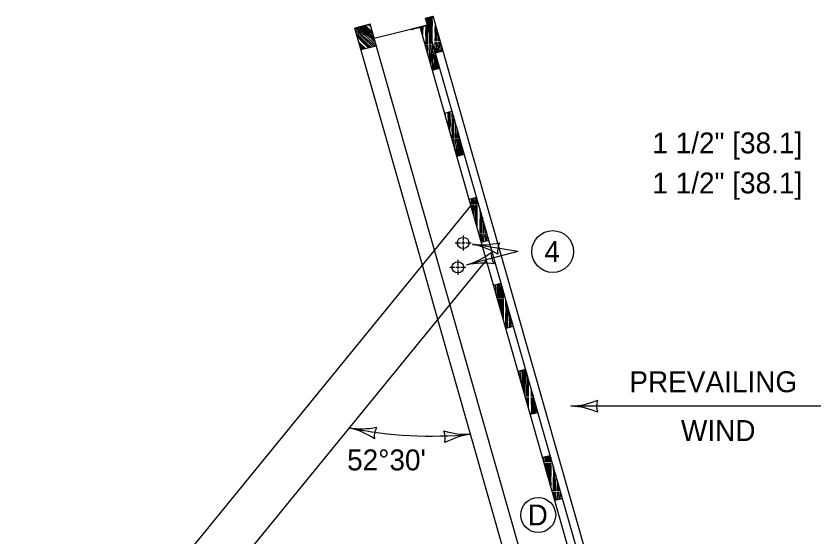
# Model space of a CAD drawing. Extents: x 49991.4 to 50021, y 49987.6 to 50011.4.
# Drawn here: x 50011.907 to 50014.217, y 49995.05 to 49996.545 of the extents above; entities that cross this region are included whole.
import ezdxf

# ---------------------------------------------------------------- set-up
doc = ezdxf.new("R2010")
doc.units = 0
for name, color, linetype in [('Level 1', 7, 'Continuous'), ('Level 2', 7, 'Continuous'), ('Level 3', 7, 'Continuous'), ('Level 4', 7, 'Continuous'), ('Level 5', 7, 'Continuous')]:
    doc.layers.add(name, color=color, linetype=linetype)

msp = doc.modelspace()

# ---------------------------------------------------------------- linework, layer by layer
at = {"layer": 'Level 1'}
for p, q in [((50013.4086, 49995.3946), (50013.0823, 49996.5389)), ((50013.0824, 49996.539), (50013.1042, 49996.5446)), ((50013.7582, 49994.2501), (50013.1042, 49996.5446)), ((50012.9234, 49996.5211), (50012.8797, 49996.51)), ((50012.8797, 49996.51), (50012.9234, 49996.5211)), ((50013.0736, 49995.8297), (50012.8797, 49996.51)), ((50012.938, 49996.3055), (50012.8797, 49996.51)), ((50012.941, 49996.4593), (50012.9234, 49996.5211)), ((50013.6869, 49993.8419), (50012.9235, 49996.5211)), ((50013.0882, 49996.5185), (50013.0008, 49996.4965)), ((50013.0408, 49996.5065), (50013.0882, 49996.5185)), ((50013.7112, 49994.2501), (50013.0664, 49996.5131)), ((50013.0008, 49996.4965), (50012.9351, 49996.48)), ((50013.0008, 49996.4965), (50013.0008, 49996.4965)), ((50013.0008, 49996.4965), (50013.0008, 49996.4965)), ((50012.8973, 49996.4483), (50012.941, 49996.4593)), ((50013.1107, 49996.4391), (50013.1327, 49996.4447)), ((50013.1016, 49996.3896), (50013.1234, 49996.3951)), ((50012.9849, 49996.3055), (50012.9761, 49996.3366)), ((50013.1367, 49996.2661), (50013.1586, 49996.2716)), ((50013.1718, 49996.1427), (50013.1937, 49996.1482)), ((50013.2071, 49996.0193), (50013.2289, 49996.0248)), ((50013.2422, 49995.896), (50013.264, 49995.9015)), ((50011.1535, 49993.4768), (50013.1083, 49995.8723)), ((50013.2774, 49995.7725), (50013.2991, 49995.778)), ((50011.2191, 49993.3474), (50013.1526, 49995.7167)), ((50013.4195, 49994.6162), (50013.1179, 49995.6741)), ((50013.3125, 49995.6491), (50013.3343, 49995.6546)), ((50013.3476, 49995.5256), (50013.3696, 49995.5312)), ((50013.3828, 49995.4023), (50013.4047, 49995.4077)), ((50013.3828, 49995.4023), (50013.4047, 49995.4077)), ((50013.6196, 49994.654), (50013.4039, 49995.411)), ((50013.4181, 49995.2789), (50013.4398, 49995.2844)), ((50013.4532, 49995.1554), (50013.475, 49995.1609))]:
    msp.add_line(p, q, dxfattribs=at)
for points in [[(50013.0841, 49996.533), (50013.0851, 49996.5396), (50013.0851, 49996.5398)], [(50013.0868, 49996.5237), (50013.089, 49996.5396), (50013.089, 49996.5407)], [(50013.0897, 49996.5134), (50013.0898, 49996.5217), (50013.0908, 49996.5396), (50013.0907, 49996.5412)], [(50013.0927, 49996.5027), (50013.0933, 49996.5171), (50013.0933, 49996.5355), (50013.0929, 49996.5417)], [(50013.0963, 49996.4902), (50013.0964, 49996.4949), (50013.0966, 49996.5197), (50013.0962, 49996.5425)], [(50013.0985, 49996.4826), (50013.0989, 49996.4892), (50013.0993, 49996.5365), (50013.0989, 49996.5433)], [(50013.1014, 49996.4724), (50013.1016, 49996.4908), (50013.1014, 49996.5067), (50013.1018, 49996.5231), (50013.1016, 49996.5396), (50013.1015, 49996.5439)], [(50012.9354, 49996.458), (50012.9146, 49996.4769), (50012.8966, 49996.494), (50012.8904, 49996.5009), (50012.8802, 49996.5101)], [(50012.9407, 49996.4605), (50012.9187, 49996.4807), (50012.9124, 49996.4863), (50012.9069, 49996.4905), (50012.9025, 49996.4936), (50012.8969, 49996.4991), (50012.8931, 49996.5043), (50012.8871, 49996.5105), (50012.8861, 49996.5116)], [(50012.9386, 49996.4677), (50012.9267, 49996.4793), (50012.918, 49996.4876), (50012.9126, 49996.4914), (50012.9088, 49996.4935), (50012.9022, 49996.4997), (50012.8939, 49996.5104), (50012.891, 49996.5129)], [(50012.9368, 49996.4741), (50012.9316, 49996.4789), (50012.9194, 49996.4899), (50012.907, 49996.5001), (50012.8966, 49996.5129), (50012.8953, 49996.514)], [(50012.9359, 49996.4775), (50012.9329, 49996.4801), (50012.9207, 49996.4911), (50012.9105, 49996.5009), (50012.8979, 49996.5142), (50012.8974, 49996.5144)], [(50012.9346, 49996.4817), (50012.9307, 49996.4854), (50012.9165, 49996.4999), (50012.9027, 49996.5129), (50012.9, 49996.5151)], [(50012.9325, 49996.4889), (50012.9169, 49996.5039), (50012.9035, 49996.516)], [(50012.9312, 49996.4936), (50012.9069, 49996.5169)], [(50012.9299, 49996.498), (50012.918, 49996.5097), (50012.9095, 49996.5175)], [(50012.9255, 49996.5138), (50012.9242, 49996.5151), (50012.9186, 49996.5199)], [(50012.9239, 49996.5194), (50012.9222, 49996.5207)], [(50013.0665, 49996.5126), (50013.0665, 49996.513)], [(50013.0698, 49996.5014), (50013.0698, 49996.5105), (50013.0698, 49996.5138)], [(50013.0723, 49996.4926), (50013.0724, 49996.5145)], [(50013.0747, 49996.4835), (50013.0746, 49996.4974), (50013.075, 49996.5139), (50013.075, 49996.5151)], [(50013.0832, 49996.5173), (50013.0834, 49996.5135), (50013.0824, 49996.4941), (50013.0828, 49996.4818), (50013.0824, 49996.4629)], [(50013.0863, 49996.5179), (50013.0868, 49996.5105), (50013.0855, 49996.4996), (50013.0858, 49996.4844), (50013.0862, 49996.4629)], [(50013.0892, 49996.5153), (50013.0896, 49996.5107), (50013.0892, 49996.4977), (50013.0882, 49996.4958), (50013.0879, 49996.4923), (50013.0881, 49996.4629)], [(50013.1101, 49996.5242), (50013.1101, 49996.5227), (50013.109, 49996.5034), (50013.1096, 49996.4911), (50013.109, 49996.4722)], [(50013.113, 49996.514), (50013.1123, 49996.509), (50013.1124, 49996.4937), (50013.1131, 49996.4722)], [(50012.9312, 49996.4568), (50012.9073, 49996.4791), (50012.8952, 49996.4911), (50012.8875, 49996.4971), (50012.8839, 49996.5008), (50012.8814, 49996.5038)], [(50012.9248, 49996.4553), (50012.9086, 49996.4703), (50012.9061, 49996.4732), (50012.9055, 49996.475), (50012.896, 49996.4845), (50012.8843, 49996.4937)], [(50012.9226, 49996.4546), (50012.913, 49996.4635), (50012.9013, 49996.4741), (50012.8942, 49996.4826), (50012.8854, 49996.4896)], [(50013.0698, 49996.5013), (50013.0698, 49996.5014)], [(50013.0723, 49996.4926), (50013.0723, 49996.4926)], [(50013.0934, 49996.5001), (50013.0934, 49996.5003)], [(50013.0934, 49996.5001), (50013.0934, 49996.4992), (50013.0938, 49996.4629)], [(50013.0971, 49996.4876), (50013.0975, 49996.4629)], [(50013.1153, 49996.5057), (50013.115, 49996.5052), (50013.1146, 49996.5015), (50013.1149, 49996.4722)], [(50013.1206, 49996.4722), (50013.1204, 49996.4879)], [(50012.9189, 49996.4538), (50012.9129, 49996.4597), (50012.9034, 49996.468), (50012.8895, 49996.4824), (50012.8869, 49996.4845)], [(50012.91, 49996.4516), (50012.9076, 49996.454), (50012.8953, 49996.4653), (50012.8913, 49996.4693)], [(50012.9072, 49996.4507), (50012.9066, 49996.4512), (50012.8926, 49996.4646)], [(50013.1032, 49996.4629), (50013.1031, 49996.4663)], [(50013.109, 49996.4701), (50013.109, 49996.4581), (50013.11, 49996.442)], [(50013.1131, 49996.4701), (50013.1133, 49996.4585), (50013.1127, 49996.4475), (50013.1133, 49996.4398)], [(50013.1149, 49996.4701), (50013.1156, 49996.4611), (50013.115, 49996.4505), (50013.1159, 49996.4405)], [(50013.1208, 49996.4417), (50013.1198, 49996.4505), (50013.12, 49996.4555), (50013.1211, 49996.4641), (50013.1206, 49996.4701)], [(50013.1239, 49996.4425), (50013.1246, 49996.4514), (50013.1244, 49996.4701)], [(50013.1244, 49996.4722), (50013.1243, 49996.4743)], [(50013.1243, 49996.4743), (50013.1243, 49996.4743)], [(50012.9043, 49996.4501), (50012.9007, 49996.4536), (50012.8939, 49996.4599)], [(50012.8999, 49996.4489), (50012.896, 49996.4528), (50012.896, 49996.4528)], [(50013.0824, 49996.4609), (50013.0824, 49996.4571)], [(50013.0862, 49996.4609), (50013.0866, 49996.4493), (50013.0862, 49996.4436)], [(50013.0862, 49996.4436), (50013.0862, 49996.4436)], [(50013.0881, 49996.4609), (50013.0888, 49996.4519), (50013.0882, 49996.4412), (50013.0889, 49996.4339)], [(50013.0938, 49996.4609), (50013.0945, 49996.4549), (50013.0932, 49996.4463), (50013.0931, 49996.4412), (50013.094, 49996.432), (50013.0934, 49996.4178)], [(50013.0975, 49996.4609), (50013.0979, 49996.442), (50013.0971, 49996.433), (50013.097, 49996.409), (50013.097, 49996.4056)], [(50013.1031, 49996.39), (50013.1029, 49996.409), (50013.1026, 49996.4172), (50013.1018, 49996.4238), (50013.101, 49996.4287), (50013.1011, 49996.4364), (50013.1023, 49996.4427), (50013.1029, 49996.4511), (50013.1032, 49996.4609)], [(50013.1072, 49996.3909), (50013.1074, 49996.4027), (50013.1075, 49996.4145), (50013.1066, 49996.4204), (50013.1054, 49996.4246), (50013.1054, 49996.4334), (50013.1075, 49996.4464), (50013.1074, 49996.4515)], [(50013.1074, 49996.4515), (50013.1074, 49996.4515)], [(50013.1106, 49996.3918), (50013.1106, 49996.3991), (50013.1102, 49996.415), (50013.1092, 49996.4304), (50013.1105, 49996.4403)], [(50013.1279, 49996.4436), (50013.1279, 49996.4457), (50013.1291, 49996.4519), (50013.1293, 49996.4562)], [(50013.1293, 49996.4562), (50013.1293, 49996.4562)], [(50013.1326, 49996.4447), (50013.1326, 49996.445)], [(50012.9021, 49996.4313), (50012.9021, 49996.4315)], [(50013.1124, 49996.3923), (50013.1124, 49996.3991), (50013.112, 49996.415), (50013.1122, 49996.4286), (50013.1124, 49996.4334)], [(50013.1146, 49996.3929), (50013.1149, 49996.4043), (50013.1157, 49996.4224)], [(50013.1157, 49996.4224), (50013.1157, 49996.4224)], [(50013.1185, 49996.3938), (50013.1188, 49996.4017), (50013.1188, 49996.4111)], [(50013.1188, 49996.4111), (50013.1188, 49996.4111)], [(50013.1211, 49996.3944), (50013.1213, 49996.3961), (50013.1213, 49996.4024)], [(50013.1392, 49996.2573), (50013.1392, 49996.2612), (50013.1391, 49996.2668)], [(50013.147, 49996.23), (50013.1478, 49996.2444), (50013.1468, 49996.2637), (50013.1468, 49996.2687)], [(50013.15, 49996.2193), (50013.15, 49996.2305), (50013.1513, 49996.2413), (50013.1503, 49996.253), (50013.1509, 49996.264), (50013.1508, 49996.2696)], [(50013.1523, 49996.2113), (50013.1522, 49996.2231), (50013.1526, 49996.2267), (50013.1536, 49996.2285), (50013.1539, 49996.2415), (50013.1526, 49996.256), (50013.1531, 49996.2666), (50013.1529, 49996.2703)], [(50013.1587, 49996.2713), (50013.1588, 49996.2696), (50013.1577, 49996.2611), (50013.1574, 49996.256), (50013.1584, 49996.2469), (50013.1579, 49996.2301), (50013.1582, 49996.1938)], [(50013.1587, 49996.2713), (50013.1587, 49996.2715)], [(50013.1622, 49996.2586), (50013.1622, 49996.2568), (50013.1616, 49996.2478), (50013.1613, 49996.2237), (50013.162, 49996.1938)], [(50013.1655, 49996.2473), (50013.1653, 49996.2435), (50013.1661, 49996.2386), (50013.1669, 49996.2319), (50013.1673, 49996.2237), (50013.1676, 49996.1938)], [(50013.15, 49996.2193), (50013.15, 49996.2193)], [(50013.1718, 49996.2249), (50013.1717, 49996.2175), (50013.1713, 49996.1938)], [(50013.175, 49996.214), (50013.175, 49996.2139), (50013.1752, 49996.1938)], [(50013.1582, 49996.1918), (50013.1583, 49996.1903)], [(50013.162, 49996.1918), (50013.1622, 49996.1768)], [(50013.1676, 49996.1918), (50013.1673, 49996.182), (50013.1666, 49996.1736), (50013.1656, 49996.1673), (50013.1656, 49996.1651)], [(50013.1713, 49996.1918), (50013.1718, 49996.1773), (50013.1698, 49996.1643), (50013.1698, 49996.1554), (50013.1709, 49996.1513), (50013.1718, 49996.1452), (50013.1718, 49996.1427)], [(50013.1752, 49996.1918), (50013.1757, 49996.1773), (50013.1735, 49996.1613), (50013.1746, 49996.1459), (50013.1747, 49996.1434)], [(50013.1769, 49996.1918), (50013.1776, 49996.1773), (50013.1766, 49996.1595), (50013.1764, 49996.1459), (50013.1764, 49996.1439)], [(50013.1769, 49996.2074), (50013.1769, 49996.1938)], [(50013.1789, 49996.2003), (50013.1789, 49996.1938)], [(50013.1789, 49996.1918), (50013.1795, 49996.1825), (50013.18, 49996.1732), (50013.18, 49996.1548), (50013.1796, 49996.1447)], [(50013.1833, 49996.1456), (50013.1833, 49996.1574), (50013.1828, 49996.1866)], [(50013.1828, 49996.1866), (50013.1828, 49996.1866)], [(50013.1859, 49996.1463), (50013.186, 49996.1743), (50013.1859, 49996.1754)], [(50013.1859, 49996.1754), (50013.1859, 49996.1754)], [(50013.1882, 49996.1468), (50013.1885, 49996.1609), (50013.1885, 49996.1665)], [(50013.1885, 49996.1665), (50013.1885, 49996.1665)], [(50013.2248, 49996.0057), (50013.2251, 49996.0239)], [(50013.2251, 49996.0239), (50013.2248, 49996.0057)], [(50013.2277, 49996.0246), (50013.2277, 49996.0228), (50013.2267, 49996.0057)], [(50013.2095, 49996.0107), (50013.2094, 49996.0199)], [(50013.2136, 49996.0211), (50013.2134, 49996.0057)], [(50013.2134, 49996.0037), (50013.2137, 49995.996)], [(50013.2172, 49996.0057), (50013.2171, 49996.0219)], [(50013.2172, 49996.0057), (50013.2171, 49996.0219)], [(50013.2171, 49995.9841), (50013.2179, 49995.9892), (50013.2172, 49996.0037)], [(50013.2189, 49996.0224), (50013.219, 49996.0057)], [(50013.2189, 49996.0224), (50013.219, 49996.0057)], [(50013.219, 49996.0037), (50013.2197, 49995.9892), (50013.219, 49995.9775)], [(50013.221, 49996.0057), (50013.221, 49996.0163), (50013.2211, 49996.0229)], [(50013.221, 49996.0057), (50013.221, 49996.0163), (50013.2211, 49996.0229)], [(50013.222, 49995.9666), (50013.222, 49995.9669), (50013.222, 49995.9851), (50013.2215, 49995.9945), (50013.221, 49996.0037)], [(50013.2248, 49996.0037), (50013.2254, 49995.9695), (50013.2253, 49995.9554)], [(50013.2267, 49996.0037), (50013.2276, 49995.9965), (50013.2281, 49995.9862), (50013.2277, 49995.9467)], [(50013.2302, 49996.0057), (50013.2303, 49996.0196)], [(50013.2302, 49996.0057), (50013.2303, 49996.0196)], [(50013.2303, 49995.9375), (50013.2305, 49995.9403), (50013.2302, 49995.9565), (50013.2306, 49995.9728), (50013.2305, 49995.9892), (50013.2302, 49996.0037)], [(50013.2303, 49996.0196), (50013.2303, 49996.0196)], [(50013.219, 49995.9775), (50013.219, 49995.9775)], [(50013.2379, 49995.993), (50013.2379, 49995.9917), (50013.2389, 49995.9725), (50013.2379, 49995.9529), (50013.2384, 49995.9407), (50013.2379, 49995.9219)], [(50013.2415, 49995.9804), (50013.2426, 49995.9695), (50013.2411, 49995.9587), (50013.2413, 49995.9433), (50013.2418, 49995.9219)], [(50013.222, 49995.9666), (50013.222, 49995.9666)], [(50013.2437, 49995.9219), (50013.2433, 49995.9511), (50013.2439, 49995.9548), (50013.2448, 49995.9566), (50013.2452, 49995.9678)], [(50013.2452, 49995.9678), (50013.2448, 49995.9566), (50013.2439, 49995.9548), (50013.2433, 49995.9511), (50013.2437, 49995.9219)], [(50013.2452, 49995.9678), (50013.2452, 49995.9678)], [(50013.2494, 49995.9219), (50013.2491, 49995.9539)], [(50013.2494, 49995.9219), (50013.2491, 49995.9539)], [(50013.2527, 49995.941), (50013.2532, 49995.9219)], [(50013.2379, 49995.9198), (50013.2379, 49995.911)], [(50013.2418, 49995.9198), (50013.242, 49995.9081), (50013.2415, 49995.8982)], [(50013.2437, 49995.9198), (50013.2444, 49995.9108), (50013.2439, 49995.9002), (50013.2442, 49995.8964)], [(50013.2489, 49995.8976), (50013.2487, 49995.9002), (50013.2488, 49995.9051), (50013.25, 49995.9138), (50013.2494, 49995.9198)], [(50013.2532, 49995.9198), (50013.2535, 49995.9009), (50013.2532, 49995.8987)], [(50013.2576, 49995.8998), (50013.2579, 49995.9015), (50013.2584, 49995.9099), (50013.2587, 49995.9198)], [(50013.2415, 49995.8982), (50013.2415, 49995.8982)], [(50013.2624, 49995.9011), (50013.263, 49995.9049)], [(50013.2779, 49995.7708), (50013.2779, 49995.7726)], [(50013.2839, 49995.7496), (50013.2838, 49995.7652), (50013.2834, 49995.7734), (50013.2832, 49995.774)], [(50013.2878, 49995.736), (50013.2883, 49995.759), (50013.2884, 49995.7706), (50013.2877, 49995.7751)], [(50013.2917, 49995.7353), (50013.2914, 49995.7555), (50013.291, 49995.7712), (50013.2908, 49995.7759)], [(50013.2935, 49995.7353), (50013.2933, 49995.7555), (50013.2929, 49995.7712), (50013.293, 49995.7764)], [(50013.2953, 49995.7353), (50013.2953, 49995.7457), (50013.2957, 49995.7605), (50013.2965, 49995.7773)], [(50013.2991, 49995.7353), (50013.2996, 49995.7579), (50013.2998, 49995.7759)], [(50013.3022, 49995.7672), (50013.3021, 49995.7524), (50013.3011, 49995.7353)], [(50013.3048, 49995.7583), (50013.3048, 49995.7538), (50013.3047, 49995.7353)], [(50013.3048, 49995.7583), (50013.3048, 49995.7583)], [(50013.2922, 49995.7206), (50013.2917, 49995.7333)], [(50013.2938, 49995.7147), (50013.294, 49995.7188), (50013.2935, 49995.7333)], [(50013.2965, 49995.7052), (50013.2965, 49995.7145), (50013.2959, 49995.724), (50013.2953, 49995.7333)], [(50013.2998, 49995.6939), (50013.2999, 49995.6989), (50013.2991, 49995.7333)], [(50013.3011, 49995.7333), (50013.302, 49995.726), (50013.3025, 49995.7158), (50013.3022, 49995.6851)], [(50013.3047, 49995.7333), (50013.3048, 49995.7188), (50013.3051, 49995.7023), (50013.3047, 49995.6859), (50013.3047, 49995.6763)], [(50013.3124, 49995.6502), (50013.3128, 49995.6702), (50013.3124, 49995.6825), (50013.3134, 49995.7019), (50013.3124, 49995.7212), (50013.3124, 49995.7317)], [(50013.3163, 49995.6499), (50013.3158, 49995.6729), (50013.3155, 49995.6881), (50013.3169, 49995.6989), (50013.316, 49995.7105), (50013.3163, 49995.7178)], [(50013.3181, 49995.6502), (50013.3178, 49995.6807), (50013.3182, 49995.6844), (50013.3191, 49995.6862), (50013.3196, 49995.6992), (50013.3186, 49995.7097)], [(50013.3238, 49995.6519), (50013.3234, 49995.6877), (50013.3237, 49995.6922)], [(50013.3276, 49995.6529), (50013.3269, 49995.6803)], [(50013.3332, 49995.6542), (50013.3332, 49995.6589)], [(50013.3332, 49995.6589), (50013.3332, 49995.6589)], [(50013.3511, 49995.5134), (50013.3514, 49995.5158), (50013.3511, 49995.5265)], [(50013.3548, 49995.5009), (50013.3545, 49995.5026), (50013.3546, 49995.5102), (50013.3558, 49995.5164), (50013.3563, 49995.5249), (50013.3564, 49995.5279)], [(50013.3609, 49995.4794), (50013.3611, 49995.4882), (50013.3601, 49995.4942), (50013.359, 49995.4983), (50013.359, 49995.5072), (50013.3611, 49995.5202), (50013.3607, 49995.529)], [(50013.3641, 49995.4679), (50013.3641, 49995.473), (50013.3637, 49995.4887), (50013.3627, 49995.5042), (50013.3648, 49995.5202), (50013.3645, 49995.5299)], [(50013.3661, 49995.4614), (50013.3659, 49995.473), (50013.3655, 49995.4887), (50013.3657, 49995.5024), (50013.3667, 49995.5202), (50013.3663, 49995.5303)], [(50013.368, 49995.4545), (50013.368, 49995.4632), (50013.3684, 49995.4781), (50013.3692, 49995.4978), (50013.3692, 49995.516), (50013.3685, 49995.5255), (50013.3683, 49995.5308)], [(50013.372, 49995.5224), (50013.3724, 49995.5004), (50013.3722, 49995.4755), (50013.3718, 49995.4528)], [(50013.372, 49995.5224), (50013.372, 49995.5224)], [(50013.3737, 49995.4528), (50013.3748, 49995.4699), (50013.3752, 49995.5115)], [(50013.3772, 49995.4528), (50013.3775, 49995.4713), (50013.3772, 49995.4874), (50013.3776, 49995.5026)], [(50013.3853, 49995.4756), (50013.3854, 49995.4717), (50013.385, 49995.4528)], [(50013.3718, 49995.4508), (50013.3719, 49995.4405)], [(50013.3752, 49995.4294), (50013.3752, 49995.4333), (50013.3746, 49995.4436), (50013.3737, 49995.4508)], [(50013.3776, 49995.4205), (50013.3775, 49995.4363), (50013.3772, 49995.4508)], [(50013.385, 49995.4508), (50013.385, 49995.4387), (50013.3861, 49995.4194), (50013.3852, 49995.4028)], [(50013.3888, 49995.4508), (50013.3891, 49995.4391), (50013.3886, 49995.4281), (50013.3896, 49995.4164), (50013.3882, 49995.4057), (50013.3882, 49995.4036)], [(50013.3886, 49995.4641), (50013.3886, 49995.4641)], [(50013.3886, 49995.4641), (50013.3888, 49995.4528)], [(50013.3908, 49995.4566), (50013.3908, 49995.4528)], [(50013.3908, 49995.4508), (50013.3914, 49995.4418), (50013.3909, 49995.4311), (50013.3923, 49995.4167), (50013.3918, 49995.4045)], [(50013.3752, 49995.4294), (50013.3752, 49995.4294)], [(50013.3961, 49995.4057), (50013.3967, 49995.4219), (50013.3957, 49995.4311), (50013.396, 49995.4361), (50013.3961, 49995.4378)], [(50013.3996, 49995.4064), (50013.3997, 49995.4229), (50013.3999, 49995.4245)], [(50013.4387, 49995.2841), (50013.4387, 49995.2824), (50013.4377, 49995.2654)], [(50013.4205, 49995.2702), (50013.4204, 49995.2795)], [(50013.4247, 49995.2806), (50013.4244, 49995.2654)], [(50013.4244, 49995.2632), (50013.4247, 49995.2556)], [(50013.4281, 49995.2814), (50013.4282, 49995.2654)], [(50013.4282, 49995.2632), (50013.4287, 49995.2487), (50013.4281, 49995.2437)], [(50013.4299, 49995.2819), (50013.43, 49995.2654)], [(50013.43, 49995.2632), (50013.4305, 49995.2487), (50013.43, 49995.237)], [(50013.4321, 49995.2824), (50013.4318, 49995.2758), (50013.4318, 49995.2654)], [(50013.4318, 49995.2632), (50013.4325, 49995.2541), (50013.4331, 49995.2446), (50013.4331, 49995.2264), (50013.4331, 49995.2261)], [(50013.4361, 49995.2835), (50013.4357, 49995.2654)], [(50013.4357, 49995.2632), (50013.4364, 49995.229), (50013.4363, 49995.2149)], [(50013.4377, 49995.2632), (50013.4385, 49995.256), (50013.439, 49995.2457), (50013.4387, 49995.2062)], [(50013.4413, 49995.2792), (50013.4411, 49995.2654)], [(50013.4411, 49995.2632), (50013.4413, 49995.2487), (50013.4416, 49995.2324), (50013.4412, 49995.2159), (50013.4413, 49995.1999), (50013.4413, 49995.197)], [(50013.4413, 49995.2792), (50013.4413, 49995.2792)], [(50013.4489, 49995.1814), (50013.4494, 49995.2003), (50013.4489, 49995.2125), (50013.4499, 49995.232), (50013.4489, 49995.2512), (50013.4489, 49995.2525)], [(50013.4489, 49995.2525), (50013.4489, 49995.2512), (50013.4499, 49995.232), (50013.4489, 49995.2125), (50013.4494, 49995.2003), (50013.4489, 49995.1814)], [(50013.4528, 49995.1814), (50013.4522, 49995.2029), (50013.4521, 49995.2181), (50013.4536, 49995.229), (50013.4525, 49995.2399)], [(50013.43, 49995.237), (50013.43, 49995.237)], [(50013.4331, 49995.226), (50013.4331, 49995.2261)], [(50013.4562, 49995.2273), (50013.4558, 49995.2161), (50013.4548, 49995.2143), (50013.4543, 49995.2107), (50013.4547, 49995.1814)], [(50013.4562, 49995.2273), (50013.4562, 49995.2273)], [(50013.46, 49995.2134), (50013.4603, 49995.1814)], [(50013.4637, 49995.2005), (50013.4641, 49995.1814)], [(50013.4489, 49995.1792), (50013.4489, 49995.1705)], [(50013.4525, 49995.1577), (50013.453, 49995.1677), (50013.4528, 49995.1792)], [(50013.4547, 49995.1792), (50013.4554, 49995.1703), (50013.4548, 49995.1597), (50013.4551, 49995.1559)], [(50013.4603, 49995.1792), (50013.461, 49995.1732), (50013.4598, 49995.1646), (50013.4595, 49995.1597), (50013.4598, 49995.1571)], [(50013.4641, 49995.1792), (50013.4645, 49995.1605), (50013.4643, 49995.1583)], [(50013.4685, 49995.1593), (50013.4689, 49995.1611), (50013.4694, 49995.1696), (50013.4697, 49995.1792)], [(50013.4525, 49995.1577), (50013.4525, 49995.1577)], [(50013.4733, 49995.1605), (50013.474, 49995.1644)]]:
    msp.add_lwpolyline(points, dxfattribs=at)
for centre in [(50013.1901, 49995.8938), (50013.1749, 49995.8238)]:
    msp.add_ellipse(centre, major_axis=(0.017, 0), ratio=0.940299, dxfattribs=at)
at = {"layer": 'Level 2'}
for centre, radius in [((50013.4471, 49995.8691), 0.06), ((50013.4056, 49995.1133), 0.05)]:
    msp.add_circle(centre, radius, dxfattribs=at)
at = {"layer": 'Level 3'}
for p, q in [((50013.3471, 49995.8691), (50013.2169, 49995.8898)), ((50013.3471, 49995.8691), (50013.201, 49995.8308)), ((50014.2166, 49995.4255), (50013.4994, 49995.4255))]:
    msp.add_line(p, q, dxfattribs=at)
for centre, radius, start, end in [((50013.242, 49996.1214), 0.233, 263.8131, 283.063), ((50013.1731, 49995.6718), 0.2223, 58.4418, 78.6254), ((50013.3435, 49995.8697), 0.0548, 153.1247, 188.847), ((50013.1308, 49996.053), 0.233, 287.5233, 306.7732), ((50013.325, 49995.8633), 0.0548, 176.8349, 212.5572), ((50013.2485, 49995.6136), 0.2223, 82.152, 102.3356), ((50013.4879, 49995.6582), 0.233, 272.8273, 292.0772), ((50013.4902, 49995.2034), 0.2223, 67.456, 87.6395), ((50013.6276, 49995.4255), 0.0548, 162.1388, 197.8612), ((50012.8981, 49995.5936), 0.233, 261.5897, 280.8396), ((50012.8118, 49995.147), 0.2223, 56.2184, 76.4019), ((50012.9898, 49995.3381), 0.0548, 150.9012, 186.6236), ((50013.1998, 49995.567), 0.2223, 252.8934, 273.0769), ((50013.0841, 49995.3328), 0.0548, 347.5762, 23.2985), ((50013.2452, 49995.1144), 0.233, 98.2647, 117.5145)]:
    msp.add_arc(centre, radius, start, end, dxfattribs=at)
msp.add_ellipse((50013.0996, 49996.4007), major_axis=(-1.1284, 0), ratio=0.940299, start_param=1.360459, end_param=1.670319, dxfattribs=at)
at = {"layer": 'Level 4'}
for p, q in [((50013.1083, 49995.8723), (50013.2125, 49996)), ((50013.1526, 49995.7167), (50013.2569, 49995.8444)), ((50013.1179, 49995.6741), (50013.0736, 49995.8297))]:
    msp.add_line(p, q, dxfattribs=at)
at = {"layer": 'Level 5'}
for p, q in [((50013.19, 49995.915), (50013.19, 49995.9012)), ((50013.1674, 49995.8938), (50013.1821, 49995.8938)), ((50013.1857, 49995.8938), (50013.1951, 49995.8938)), ((50013.19, 49995.8989), (50013.19, 49995.8897)), ((50013.19, 49995.8863), (50013.19, 49995.8725)), ((50013.198, 49995.8938), (50013.2127, 49995.8938)), ((50013.1748, 49995.845), (50013.1748, 49995.8312)), ((50013.1522, 49995.8238), (50013.1669, 49995.8238)), ((50013.1705, 49995.8238), (50013.1799, 49995.8238)), ((50013.1748, 49995.8289), (50013.1748, 49995.8197)), ((50013.1748, 49995.8163), (50013.1748, 49995.8025)), ((50013.1828, 49995.8238), (50013.1975, 49995.8238))]:
    msp.add_line(p, q, dxfattribs=at)

# ---------------------------------------------------------------- texts
at = {"layer": 'Level 2'}
for s, p in [('1 1/2" [38.1]', (50013.733, 49996.1506)), ('1 1/2" [38.1]', (50013.733, 49996.0358)), ('4', (50013.4231, 49995.8391)), ('PREVAILING', (50013.6669, 49995.4655)), ('WIND', (50013.815, 49995.3255)), ("52°30'", (50012.8572, 49995.2413)), ('D', (50013.3752, 49995.0833))]:
    msp.add_text(s, height=0.06, dxfattribs=at).set_placement(p)

doc.saveas('drawing.dxf')
